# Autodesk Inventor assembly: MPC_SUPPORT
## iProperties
Shininess: 64.0
Length Units: 11269
Angle Units: 11279
Time Units: 11290
Mass Units: 11283
Length Display Precision: 3
Angle Display Precision: 2
Compacted: True
Created: 2004-08
Part Number: MPC_SUPPORT
Document SubType Name: Assembly
Designer: John Blackburn
Manufacturer: Standard
Standards Organization: Custom
Density: 0.0
Volumn: 0.0
Area: 0.0
PropertySet Name: Model Information
Control State: 0
Master: False
Checked Out: False
Author: John Blackburn
